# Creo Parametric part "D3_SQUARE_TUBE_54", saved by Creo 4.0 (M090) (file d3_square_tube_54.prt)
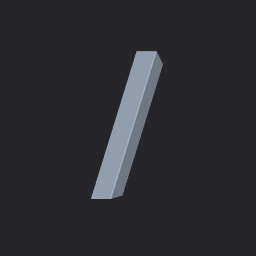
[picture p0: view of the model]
Units: Custom; MM, KILOGRAM, SECS
Materials in the file: STEEL

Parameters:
  BUW_NAME = "SQUARE TUBE"
  BUW_TYPE = "DIN EN 10210"
  BUW_SIZE = "60x60x3.0"
  BUW_LENGTH_STR = "500"
  PTC_MATERIAL_NAME = "STEEL"
  BUW_PROFIL_TYPE = "square_tube"
  BUW_PROFILE_PATH = "parts/profiles/steel_beams_mm/"
  BUW_PROFILE_NAME_LANG = "SQUARE TUBE"
  BUW_TAB_SEL_INFO = "2  0 2  3 19"
  MITRE_SYM_X_S = "|"
  MITRE_SYM_X_E = "\"
  MITRE_SYM_X = "|---\"
  MITRE_BOM_X = "X |---\"
  MITRE_SYM_Y_S = "|"
  MITRE_SYM_Y_E = "|"
  MITRE_SYM_Y = "|---|"
  BUW_DOUBLE_TO_STR_INFO = "X_ROT_S2 2 X_ROT_E2 2 Y_ROT_S2 2 Y_ROT_E2 2"
  X_ROT_S2_STR = "90"
  X_ROT_E2_STR = "45"
  Y_ROT_S2_STR = "90"
  Y_ROT_E2_STR = "90"
  BOM_ANGLE_E = "X 45°"
  EFX_ITEM_NR = "7"
  PROFIL_RASTER_POS = "X_0"
  BUW_OBJECT_ROLE = "PROFIL_SYSTEM_BORE_END_POINTS"
  PRO_UNIT_SYS = "Custom"

Other parameters: BUW_LENGTH, X_ROT_S2, X_ROT_E2, Y_ROT_S2, Y_ROT_E2, D8, D93, D94, d26, d8, d93, d94, d98, D98, D0, D4, D1, D5, SHEAR_MODULUS, THERM_EXPANSION_REF_TEMPERATURE, STRUCTURAL_DAMPING_COEFFICIENT, STRESS_LIMIT_FOR_TENSION, STRESS_LIMIT_FOR_COMPRESSION, STRESS_LIMIT_FOR_SHEAR, EMISSIVITY

Created from: SQUARE_TUBE.PRT

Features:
  1. datum plane "YZ"
  2. datum plane "XZ"
  3. datum plane "XY"
  4. coordinate system
  5. coordinate system
  6. coordinate system
  7. coordinate system
  8. datum plane "DTM3"
  9. datum plane "DTM4"
  10. datum plane "DTM5"
  11. protrusion
  12. round
  13. round
  14. datum axis
  15. datum point "PNT0"
  16. datum point

Other named items: PROFIL_CUT_QUILT, PROFILE_LENGTH_DIM, CONTACT_SURF_3, CONTACT_SURF_2, CONTACT_SURF_1, CONTACT_SURF_0, E, START_SURFACE, END_SURFACE, SIDE_SURF_3, SIDE_SURF_0, SIDE_SURF_1, SIDE_SURF_2, EDGE_7_S, EDGE_7_E, EDGE_1_S, EDGE_1_E, EDGE_3_S, EDGE_3_E, EDGE_5_S, EDGE_5_E, EDGE_6_S, EDGE_4_S, EDGE_2_S, EDGE_0_S, EDGE_6_E, EDGE_4_E, EDGE_2_E, EDGE_0_E, CS0, CS_S, CS_E, CS3

Named dimensions: X_ROT_S, Y_ROT_S, Z_OFF_S, X_ROT_E, Y_ROT_E, Z_OFF_E, PC_L, BUW_LENGTH_Z_MIN, BUW_LENGTH_DIM

Layers: 00_PROFIL_DATUM, 00_PROFIL_DRW_HIDE, 00_PROFIL_END_CSYS, 00_PROFIL_GEOMETRY, 00_PROFIL_QUILT, 00_PROFIL_SIZE_NOTE

Surfaces: 10 plane, 8 cylinder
